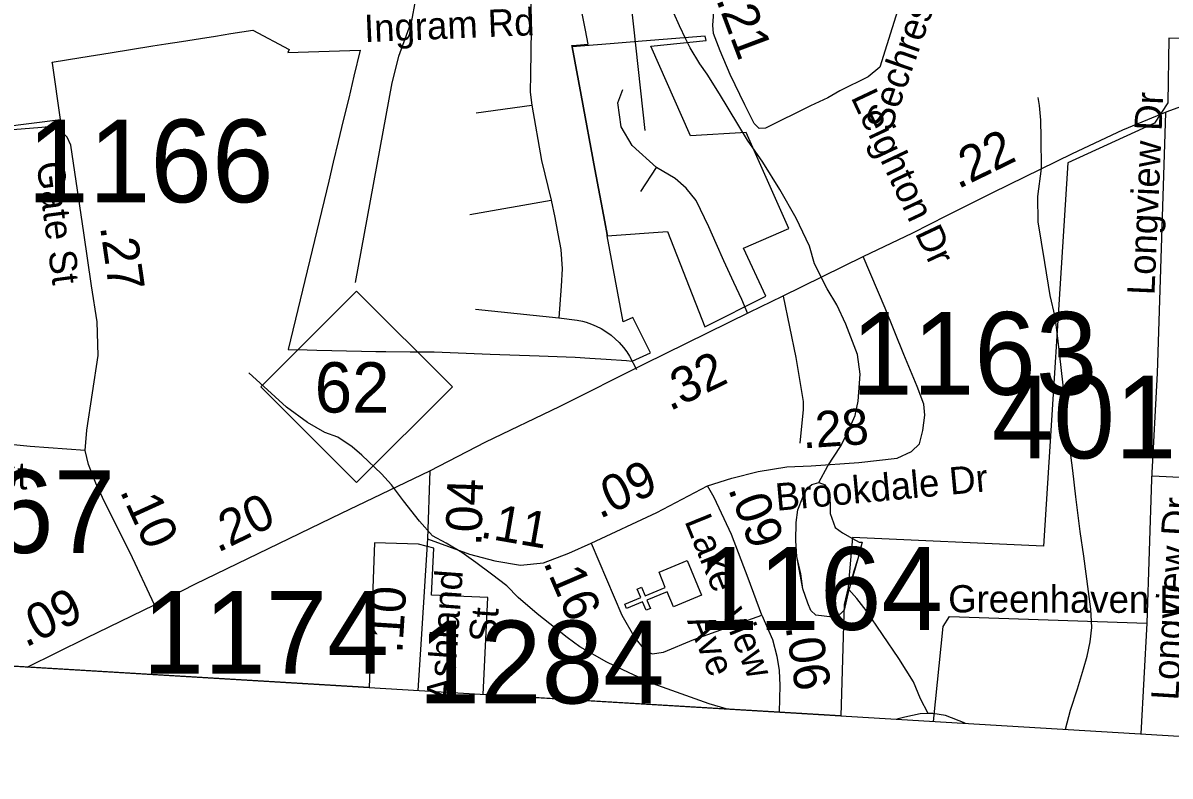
# Model space of a CAD drawing. Extents: x 1662474 to 1856135, y 779280 to 917889.
# Drawn here: x 1715176 to 1719166, y 789845 to 792465 of the extents above; entities that cross this region are included whole.
import ezdxf

# ---------------------------------------------------------------- set-up
doc = ezdxf.new("R2010")
doc.units = 0
for name, color, linetype in [('Cogo Default Point CELL', 7, 'Continuous'), ('Exist Boundary Political City Limit New', 7, 'Continuous'), ('Exist Boundary Political CountyLine', 7, 'Continuous'), ('Exist Civil Demographics Community Label', 7, 'Continuous'), ('Exist Cultural Church CELL', 7, 'Continuous'), ('Exist Hydrographic Misc Water Feature', 7, 'Continuous'), ('Exist Road Non-System Type 51', 7, 'Continuous'), ('Exist Road Non-System Type 51 Label', 7, 'Continuous'), ('Exist Road Primary NC Attributed', 7, 'Continuous'), ('Exist Road Primary NC Service Mileage Hundredths English Label', 7, 'Continuous'), ('Exist Road Primary NC Shield CELL', 7, 'Continuous'), ('Exist Road Primary NC Shield Number Label', 7, 'Continuous'), ('Exist Road Secondary Mileage Tenths English Label', 7, 'Continuous'), ('Exist Road Secondary Type 51 Attributed', 7, 'Continuous'), ('Exist Road Secondary Type 51 Label', 7, 'Continuous'), ('Map Preparation Boundary City Limit Buffer Line', 7, 'Continuous'), ('Prop DGN Element Guardrail', 7, 'Continuous'), ('Prop Guardrail', 7, 'Continuous')]:
    doc.layers.add(name, color=color, linetype=linetype)

msp = doc.modelspace()

# ---------------------------------------------------------------- linework, layer by layer
at = {"layer": 'Exist Boundary Political City Limit New'}
for points in [[(1717086.6, 792381.8), (1717085.8, 792386.7), (1717087.4, 792386.8), (1717141.9, 792391.2), (1717132.2, 792440.1), (1717060.5, 792803.9), (1716963.8, 792784.6), (1716871.8, 792766.3), (1716769.2, 792745.9), (1716596.4, 792717.6), (1716491.9, 792700.2), (1716445.8, 792700), (1716477.5, 792767.9), (1716831.2, 793600.1), (1716871.4, 793602.7), (1716891, 793620.2), (1716897.5, 793635), (1717059.1, 794003.9)], [(1719308, 792409), (1719161.8, 792412.2), (1719157.8, 792186.7), (1719111.9, 792116.1), (1718811, 791978.6), (1718725.5, 790644.5), (1718062, 790675.1), (1718048.6, 790529.6), (1718046.4, 790501.2), (1718032, 790441.4), (1718031.2, 790408), (1718020.9, 790054.2), (1716776.4, 790128.8), (1716792.6, 790466.4), (1716596.8, 790473.7), (1716604.8, 790637.6), (1716551.5, 790651.9), (1716399, 790656.1), (1716380.2, 790152.6), (1715081.1, 790230.6)], [(1715104.5, 792103.3), (1715306.6, 792129.2), (1715278.4, 792325.1), (1715277.9, 792328.9), (1715377, 792344.9), (1715479.9, 792361.5), (1715628, 792385.4), (1715673.4, 792392.5), (1715727, 792400.9), (1715793.1, 792411.2), (1715845.2, 792419.4), (1715898.8, 792427.8), (1715975.2, 792439.9), (1716102.2, 792372.4), (1716097, 792362.6), (1716349.4, 792370.9), (1716327.5, 792280.1), (1716309.1, 792203.6), (1716290.4, 792125.3), (1716272.9, 792052.4), (1716255.6, 791980.8), (1716239.8, 791914.4), (1716099.1, 791329.1), (1716164.8, 791327.5), (1716198.5, 791326.7), (1716353.2, 791323.1), (1716403.9, 791322.2), (1716438.5, 791321.8), (1716523.1, 791320.4), (1716574.5, 791321.2), (1716605.9, 791320.2), (1716801.5, 791312.9), (1716971.8, 791306.5), (1717097.4, 791301.8), (1717148.2, 791298.5), (1717204.8, 791294.8), (1717275.8, 791290.2), (1717295.5, 791288.6), (1717359.1, 791317.1), (1717297.2, 791440.6), (1717263.9, 791425.1), (1717208.5, 791723.8)], [(1717360, 792384.8), (1717552, 792403.7), (1717549.6, 792419.5), (1717329.6, 792401.5), (1717218.8, 792392.5), (1717086.6, 792381.8)], [(1717086.6, 792381.8), (1717117.6, 792214.1), (1717165.5, 791955.9), (1717199.5, 791772.6), (1717207.6, 791728.8), (1717208.5, 791723.8)], [(1717208.5, 791723.8), (1717207.6, 791728.8), (1717199.5, 791772.6), (1717165.5, 791955.9), (1717117.6, 792214.1), (1717086.6, 792381.8)], [(1717208.5, 791723.8), (1717417.8, 791739.4), (1717547.6, 791407.2), (1717760.4, 791514.4), (1717682.8, 791681.9), (1717839.5, 791749.4), (1717692.2, 792083.4), (1717498.5, 792072.2), (1717360, 792384.8)]]:
    msp.add_lwpolyline(points, dxfattribs=at)
at = {"layer": 'Exist Boundary Political CountyLine'}
msp.add_lwpolyline([(1690037.5, 791664.5), (1701364.2, 790957.5), (1714716, 790252.3), (1740499.2, 788706.5), (1750629.1, 788065.3), (1759370.2, 787540.1), (1762189.4, 787333), (1768414.3, 786933.6), (1776472.8, 786425.7), (1794607.1, 785397.2), (1814974.6, 784258.7), (1839558.3, 782880.6)], dxfattribs=at)
at = {"layer": 'Exist Civil Demographics Community Label'}
msp.add_lwpolyline([(1717340.7, 792090.9), (1717237.1, 793036.3), (1716252.9, 794033.4)], dxfattribs=at)
at = {"layer": 'Exist Cultural Church CELL'}
msp.add_lwpolyline([(1717438.4, 790433.5), (1717416.5, 790486.1), (1717346.2, 790457), (1717358.4, 790427.4), (1717343.6, 790421.3), (1717331.4, 790450.9), (1717275.8, 790427.9), (1717269.7, 790442.7), (1717325.3, 790465.7), (1717313, 790495.3), (1717327.8, 790501.4), (1717340, 790471.8), (1717410.4, 790500.9), (1717388.5, 790554.2), (1717486.8, 790594.9), (1717536.8, 790474.2)], close=True, dxfattribs=at)
at = {"layer": 'Exist Hydrographic Misc Water Feature'}
for points in [[(1717944.7, 790866.2), (1717975.4, 790924), (1718020, 790991.6), (1718044.4, 791039.4), (1718071, 791099.1), (1718081.5, 791149), (1718088.3, 791243), (1718079, 791311.1), (1718038, 791417.5), (1718006.6, 791483.9), (1717973.1, 791540.2), (1717929.9, 791626.6), (1717912.5, 791688.8), (1717865.4, 791785.3), (1717808.3, 791885.9), (1717749.2, 791980.5), (1717696, 792056.9), (1717599.3, 792218), (1717556.1, 792286.3), (1717530.3, 792322.6), (1717497, 792378.9), (1717481.2, 792409.1), (1717459.6, 792455.3), (1717440, 792499.5)], [(1718802.2, 790007.3), (1718819.5, 790073.8), (1718844.3, 790147.5), (1718864.9, 790217.4), (1718877.3, 790261.2), (1718887.7, 790311.1), (1718894.2, 790361.2), (1718890.8, 790425.1), (1718866.6, 790609.5), (1718853.4, 790695.6), (1718838.5, 790815.8), (1718827.4, 790907.9), (1718814.3, 791014.1), (1718794.2, 791204.3), (1718775.8, 791368.5), (1718766.5, 791442.7), (1718749.1, 791516.9), (1718730.3, 791631), (1718707.5, 791773.3), (1718706.4, 791861.3), (1718719.3, 791959.2), (1718718.3, 792065.3), (1718716.8, 792127.3), (1718711.4, 792177.4), (1718707.6, 792205.4)], [(1717622.6, 790078.1), (1717563.3, 790095.6), (1717368, 790165.5), (1717284.3, 790204.2), (1717206.6, 790241), (1717113.1, 790294), (1717069.3, 790326.4), (1716964.2, 790409.4), (1716898.5, 790466), (1716859, 790506.4), (1716805.3, 790546.9), (1716751.7, 790587.5), (1716702.1, 790621.9), (1716648.4, 790654.4), (1716600.6, 790680.9), (1716555.1, 790731.3), (1716499.7, 790801.9), (1716458.2, 790858.3), (1716422.6, 790896.7), (1716355.1, 790961.3), (1716321.4, 790989.6), (1716271.7, 791024.1), (1716225.9, 791040.5), (1716166.2, 791075.1), (1716092.7, 791127.8), (1715961.6, 791247.1)], [(1718049.2, 790493.2), (1718036.9, 790447.3), (1718032.6, 790421.3), (1718018.4, 790407.4), (1717992.4, 790397.7), (1717934.4, 790404.2), (1717916.5, 790420.4), (1717906.7, 790446.5), (1717889.2, 790496.6), (1717881.8, 790548.8), (1717868.2, 790608.9), (1717864.7, 790662.9), (1717865.4, 790727), (1717871.8, 790770.9), (1717888.2, 790814.8), (1717900.5, 790842.7), (1717920.6, 790858.5), (1717944.7, 790866.2)], [(1718049.2, 790493.2), (1718032.6, 790421.3), (1718018.4, 790407.4), (1717992.4, 790397.7), (1717934.4, 790404.2), (1717916.5, 790420.4), (1717906.7, 790446.5), (1717889.2, 790496.6), (1717868.2, 790608.9), (1717864.7, 790662.9), (1717865.4, 790727), (1717871.8, 790770.9), (1717888.2, 790814.8), (1717900.5, 790842.7), (1717920.6, 790858.5), (1717944.7, 790866.2)], [(1717944.7, 790866.2), (1717966.6, 790858.1), (1717976.5, 790831.9), (1717984.1, 790795.8), (1717983.8, 790757.8), (1718001.2, 790709.6), (1718027.1, 790691.4), (1718061, 790671.1), (1718084.9, 790658.9), (1718094.8, 790658.8), (1718080.2, 790600.9), (1718065.9, 790557), (1718051.3, 790499.1), (1718049.2, 790493.2)], [(1717944.7, 790866.2), (1717966.6, 790858.1), (1717976.5, 790831.9), (1717984.1, 790795.8), (1717983.8, 790757.8), (1718001.2, 790709.6), (1718027.1, 790691.4), (1718061, 790671.1), (1718084.9, 790658.9), (1718094.8, 790658.8), (1718080.2, 790600.9), (1718051.3, 790499.1), (1718049.2, 790493.2)], [(1718325.2, 790062.4), (1718297.7, 790112.7), (1718274.2, 790172.9), (1718223, 790253.4), (1718108.6, 790420.6), (1718077, 790462.9), (1718049.2, 790493.2)], [(1718325.2, 790062.4), (1718297.2, 790060.7), (1718243.1, 790049.2), (1718215.4, 790042.5)], [(1718452.9, 790028.3), (1718385.3, 790055.8), (1718341.2, 790062.2), (1718325.2, 790062.4)]]:
    msp.add_lwpolyline(points, dxfattribs=at)
at = {"layer": 'Exist Road Non-System Type 51'}
for p, q in [((1716751.9, 792152.4), (1716946.1, 792179.1)), ((1717324.9, 791878.9), (1717379.4, 791962.4)), ((1716730.9, 791798.9), (1717013.9, 791847.9)), ((1716749.8, 791468.6), (1717040.4, 791439.2)), ((1719101.6, 790877.6), (1719085.4, 790377)), ((1719085.4, 790377), (1719064.8, 789991.6))]:
    msp.add_line(p, q, dxfattribs=at)
for points in [[(1716911.4, 792809.2), (1716921.4, 792719), (1716931.4, 792659.9), (1716938.8, 792606.7), (1716942.9, 792551), (1716943.8, 792442.9), (1716941.1, 792287), (1716939.9, 792224), (1716946.1, 792179.1)], [(1716538.2, 792746), (1716540.4, 792541.6), (1716527.8, 792472), (1716481.9, 792347.9), (1716459, 792256.2), (1716331.9, 791561.8)], [(1717379.4, 791962.4), (1717294.9, 792038.7), (1717257.1, 792103.8), (1717245.6, 792187), (1717263.1, 792233.9)], [(1716946.1, 792179.1), (1716980.2, 791987), (1717013.9, 791847.9)], [(1719150, 792151.9), (1719121.6, 791246.4), (1719101.6, 790877.6)], [(1717697.5, 791452.6), (1717676.2, 791503), (1717649, 791562.4), (1717614.4, 791637.9), (1717587.4, 791698), (1717561.9, 791755.5), (1717517.8, 791847.1), (1717483.1, 791890.2), (1717445, 791924), (1717379.4, 791962.4)], [(1717013.9, 791847.9), (1717026.1, 791787.8), (1717036.4, 791731.6), (1717047.4, 791676.2), (1717051.4, 791609.9), (1717048.1, 791548.7), (1717040.4, 791439.2)], [(1717820.9, 791514), (1717864.8, 791300.4), (1717890.1, 791147.9), (1717890.1, 791120.6), (1717878.1, 791002.8)], [(1717040.4, 791439.2), (1717103.9, 791431.4), (1717121.9, 791427.2), (1717135.6, 791423.8), (1717153.1, 791417.4), (1717170.2, 791410.4), (1717186.8, 791401.9), (1717206.8, 791389.6), (1717221.6, 791378.4), (1717236.1, 791366.5), (1717249.5, 791353.7), (1717265, 791335.9), (1717276, 791320.9), (1717286, 791305.1), (1717309.6, 791259.4)], [(1718343.7, 790034.8), (1718376.8, 790365), (1718398.6, 790399.4), (1719085.4, 790377)]]:
    msp.add_lwpolyline(points, dxfattribs=at)
at = {"layer": 'Exist Road Primary NC Attributed'}
for points in [[(1718098.4, 791652.4), (1718271.2, 791735.3), (1718389.1, 791795.3), (1718549.4, 791875.2), (1718827.2, 792011.1), (1719002, 792093), (1719155.8, 792156.9), (1719238.8, 792186.9), (1719373.3, 792225.9), (1719492, 792249.8), (1719553, 792258.8), (1719618.9, 792264.8), (1719676.8, 792271.8), (1719736.8, 792274.8)], [(1716590.8, 790906.9), (1716786.1, 791007), (1717042.4, 791130.9), (1717338.1, 791278.8), (1717703.2, 791458.6), (1717818.1, 791514.5), (1718098.4, 791652.4)], [(1715633.7, 790440.6), (1715776.6, 790513.5), (1715994.4, 790619.4), (1716284, 790759.1), (1716590.8, 790906.9)], [(1715190.7, 790223.9), (1715397.5, 790325.7), (1715633.7, 790440.6)]]:
    msp.add_lwpolyline(points, dxfattribs=at)
at = {"layer": 'Exist Road Primary NC Shield CELL'}
msp.add_lwpolyline([(1716003.6, 791199.2), (1716336.6, 791532.2), (1716669.6, 791199.2), (1716336.6, 790866.2)], close=True, dxfattribs=at)
at = {"layer": 'Exist Road Secondary Type 51 Attributed'}
msp.add_line((1716590.8, 790906.9), (1716583.5, 790670.5), dxfattribs=at)
for points in [[(1718379.1, 793101), (1718293.5, 792780.1), (1718229.2, 792543.1), (1718224.4, 792525.9), (1718156.4, 792311.8), (1718116.1, 792278.1), (1718017.4, 792228.8), (1717975.5, 792204.7), (1717915.9, 792176.4)], [(1717915.9, 792176.4), (1717758.6, 792099.4), (1717737, 792097.5), (1717719.1, 792115.4), (1717686.6, 792180.6), (1717636.1, 792286.1), (1717600.7, 792367.7), (1717577.7, 792428.7), (1717575.8, 792457.4), (1717577.7, 792487.9), (1717576.8, 792512.7), (1717576.2, 792533.1), (1717576, 792697.2), (1717583.9, 792974.1)], [(1715392.5, 790977.1), (1715398.5, 791048), (1715438.2, 791308.3), (1715434.4, 791424.6), (1715414.4, 791550.5), (1715387.5, 791734.3), (1715342.5, 792039.7), (1715329.6, 792068.2), (1715303.7, 792094), (1715277.8, 792104.4), (1715241.6, 792101.8), (1715081.3, 792088.8)], [(1717556.8, 790854.7), (1717641.3, 790881.6), (1717733.5, 790904.6), (1717833.3, 790920), (1717917.8, 790923.8), (1718083, 790935.3), (1718217.4, 790950.7), (1718267.3, 790973.7), (1718294.2, 791000.6), (1718305.7, 791046.6), (1718313.4, 791100.3), (1718309.6, 791138.7), (1718286.5, 791200.1), (1718240.4, 791311.4), (1718175.1, 791472.6), (1718098.4, 791652.4)], [(1715392.5, 790977.1), (1715200.7, 790991.1), (1715071.8, 791004), (1714969.9, 791004), (1714901.4, 790996), (1714836.1, 790973.2), (1714757.7, 790937.3), (1714608.7, 790843.2)], [(1715633.7, 790440.6), (1715548.8, 790621.4), (1715460.9, 790796.2), (1715429.4, 790864.2), (1715404.5, 790929.1), (1715392.5, 790977.1)], [(1719736.8, 790857.2), (1719575.9, 790865.2), (1719104.9, 790888.2)], [(1717152, 790655.1), (1717380.4, 790761.8), (1717556.8, 790854.7)], [(1717746.1, 790404.2), (1717698.7, 790533.1), (1717640.8, 790685.6), (1717580.3, 790814.4), (1717556.8, 790854.7)], [(1716583.5, 790670.5), (1716561, 790320.8), (1716549.5, 790142.4)], [(1716583.5, 790670.5), (1716729.5, 790616.8), (1716817.8, 790593.7), (1716906.1, 790578.4), (1716986.8, 790586.1), (1717075.1, 790620.6), (1717152, 790655.1)], [(1717152, 790655.1), (1717259.3, 790404.2), (1717304.1, 790325.4), (1717338.3, 790283.3), (1717364.6, 790270.2), (1717404, 790275.4), (1717509.3, 790320.1), (1717746.1, 790404.2)], [(1717746.1, 790404.2), (1717782.9, 790320.1), (1717798.7, 790262.3), (1717806.6, 790212.3), (1717809.2, 790159.7), (1717806.6, 790067)]]:
    msp.add_lwpolyline(points, dxfattribs=at)
at = {"layer": 'Map Preparation Boundary City Limit Buffer Line'}
for points in [[(1717086.6, 792381.8), (1717085.8, 792386.7), (1717087.4, 792386.8), (1717141.9, 792391.2), (1717132.2, 792440.1), (1717060.5, 792803.9), (1716963.8, 792784.6), (1716871.8, 792766.3), (1716769.2, 792745.9), (1716596.4, 792717.6), (1716491.9, 792700.2), (1716445.8, 792700), (1716477.5, 792767.9), (1716831.2, 793600.1), (1716871.4, 793602.7), (1716891, 793620.2), (1716897.5, 793635), (1717059.1, 794003.9)], [(1719308, 792409), (1719161.8, 792412.2), (1719157.8, 792186.7), (1719111.9, 792116.1), (1718811, 791978.6), (1718725.5, 790644.5), (1718062, 790675.1), (1718048.6, 790529.6), (1718046.4, 790501.2), (1718032, 790441.4), (1718031.2, 790408), (1718020.9, 790054.2), (1716776.4, 790128.8), (1716792.6, 790466.4), (1716596.8, 790473.7), (1716604.8, 790637.6), (1716551.5, 790651.9), (1716399, 790656.1), (1716380.2, 790152.6), (1715081.1, 790230.6)], [(1715104.5, 792103.3), (1715306.6, 792129.2), (1715278.4, 792325.1), (1715277.9, 792328.9), (1715377, 792344.9), (1715479.9, 792361.5), (1715628, 792385.4), (1715673.4, 792392.5), (1715727, 792400.9), (1715793.1, 792411.2), (1715845.2, 792419.4), (1715898.8, 792427.8), (1715975.2, 792439.9), (1716102.2, 792372.4), (1716097, 792362.6), (1716349.4, 792370.9), (1716327.5, 792280.1), (1716309.1, 792203.6), (1716290.4, 792125.3), (1716272.9, 792052.4), (1716255.6, 791980.8), (1716239.8, 791914.4), (1716099.1, 791329.1), (1716164.8, 791327.5), (1716198.5, 791326.7), (1716353.2, 791323.1), (1716403.9, 791322.2), (1716438.5, 791321.8), (1716523.1, 791320.4), (1716574.5, 791321.2), (1716605.9, 791320.2), (1716801.5, 791312.9), (1716971.8, 791306.5), (1717097.4, 791301.8), (1717148.2, 791298.5), (1717204.8, 791294.8), (1717275.8, 791290.2), (1717295.5, 791288.6), (1717359.1, 791317.1), (1717297.2, 791440.6), (1717263.9, 791425.1), (1717208.5, 791723.8)], [(1717360, 792384.8), (1717552, 792403.7), (1717549.6, 792419.5), (1717329.6, 792401.5), (1717218.8, 792392.5), (1717086.6, 792381.8)], [(1717086.6, 792381.8), (1717117.6, 792214.1), (1717165.5, 791955.9), (1717199.5, 791772.6), (1717207.6, 791728.8), (1717208.5, 791723.8)], [(1717208.5, 791723.8), (1717207.6, 791728.8), (1717199.5, 791772.6), (1717165.5, 791955.9), (1717117.6, 792214.1), (1717086.6, 792381.8)], [(1717208.5, 791723.8), (1717417.8, 791739.4), (1717547.6, 791407.2), (1717760.4, 791514.4), (1717682.8, 791681.9), (1717839.5, 791749.4), (1717692.2, 792083.4), (1717498.5, 792072.2), (1717360, 792384.8)]]:
    msp.add_lwpolyline(points, dxfattribs=at)

# ---------------------------------------------------------------- texts
at = {"layer": 'Cogo Default Point CELL'}
for s, p in [('1166', (1715190.9, 791841.1)), ('1163', (1718056.6, 791171.3)), ('4013', (1718546.1, 790950.1)), ('1167', (1714640.1, 790620.9)), ('1164', (1717519.6, 790353.3)), ('1174', (1715591.7, 790201)), ('1284', (1716551.4, 790097.3))]:
    msp.add_text(s, height=288, dxfattribs=at).set_placement(p)
at = {"layer": 'Exist Road Non-System Type 51 Label'}
for s, rotation, p in [('Ingram Rd', 2.3864, (1716364.5, 792398.1)), ('Leighton Dr', 295.2559, (1718054.4, 792206.4)), ('Longview Dr', 87.4769, (1719111.6, 791516.7)), ('Longview Dr', 86.5162, (1719194.7, 790106.5)), ('Greenhaven Dr', 359.8453, (1718394.3, 790414))]:
    msp.add_text(s, height=95, rotation=rotation, dxfattribs=at).set_placement(p)
at = {"layer": 'Exist Road Primary NC Service Mileage Hundredths English Label'}
for s, rotation, p in [('.22', 26.0683, (1718428.6, 791885.7)), ('.32', 26.2191, (1717426.3, 791113.2))]:
    msp.add_text(s, height=125, rotation=rotation, dxfattribs=at).set_placement(p)
at = {"layer": 'Exist Road Primary NC Shield Number Label'}
msp.add_text('62', height=175, dxfattribs=at).set_placement((1716190.8, 791109.5))
at = {"layer": 'Exist Road Secondary Mileage Tenths English Label'}
for s, rotation, p in [('.21', 290.5699, (1717585.9, 792547.1)), ('.27', 278.2132, (1715443.9, 791755.9)), ('.10', 294.6064, (1715511.4, 790836.6)), ('.06', 278.9794, (1717828.1, 790364.8))]:
    msp.add_text(s, height=125, rotation=rotation, dxfattribs=at).set_placement(p)
at = {"layer": 'Exist Road Secondary Type 51 Label'}
for s, rotation, p in [('Sechrest Cir', 70.7721, (1718193.6, 792082.6)), ('Gate St', 277.5765, (1715222.9, 791977.2)), ('Dill St', 0.5786, (1714859.9, 790838.8)), ('Brookdale Dr', 5.2941, (1717797.7, 790767.4)), ('Lake  view', 292.0828, (1717476.1, 790731.9)), ('Ashland', 85.8175, (1716673, 790100.6)), (' St', 85.8175, (1716819.6, 790272.1)), ('        Ave', 292.0828, (1717378.9, 790646.9))]:
    msp.add_text(s, height=95, rotation=rotation, dxfattribs=at).set_placement(p)
at = {"layer": 'Prop DGN Element Guardrail'}
for s, rotation, p in [('.28', 3.988, (1717889.6, 790984.5)), ('.09', 25.0352, (1717182.1, 790738.2)), ('.04', 88.2363, (1716770.3, 790644.9)), ('.09', 290.7866, (1717627.7, 790844)), ('.11', 350.1415, (1716762.9, 790675.5)), ('.16', 293.1698, (1716984.9, 790587.8)), ('.10', 86.3134, (1716495.1, 790269.6))]:
    msp.add_text(s, height=125, rotation=rotation, dxfattribs=at).set_placement(p)
at = {"layer": 'Prop Guardrail'}
for s, rotation, p in [('.20', 25.7544, (1715853.2, 790620.7)), ('.09', 26.222, (1715185.1, 790290.8))]:
    msp.add_text(s, height=125, rotation=rotation, dxfattribs=at).set_placement(p)

doc.saveas('drawing.dxf')
